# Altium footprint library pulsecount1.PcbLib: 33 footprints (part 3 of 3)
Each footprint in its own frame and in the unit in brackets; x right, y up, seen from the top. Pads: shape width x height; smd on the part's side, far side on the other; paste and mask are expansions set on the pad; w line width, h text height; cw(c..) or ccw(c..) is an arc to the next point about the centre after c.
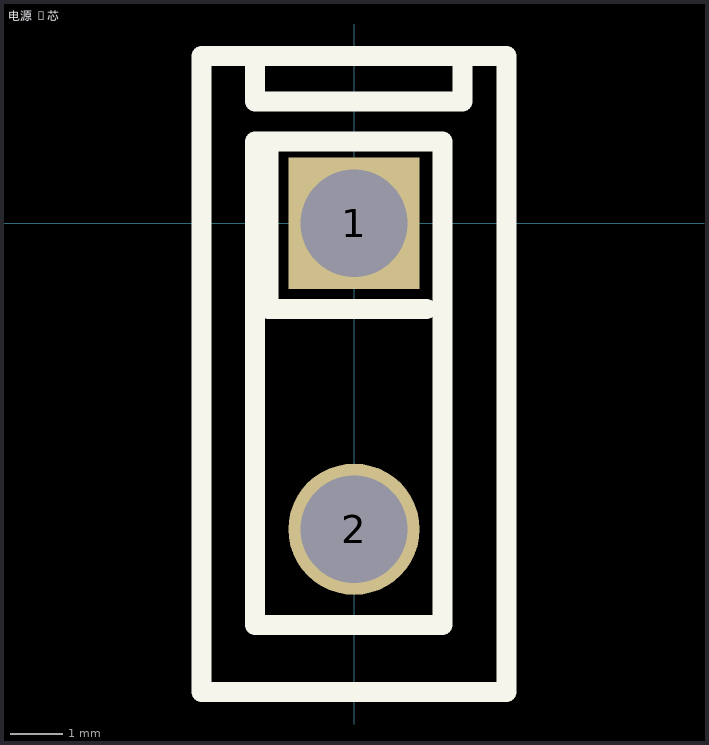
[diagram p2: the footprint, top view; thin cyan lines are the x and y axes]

## 电源 2芯 [mil]
pads (2):
  rect 98x98 hole 80: 1(0,0)
  round 98 hole 80: 2(0,-228.35)
Top Overlay:
  lines w15: -74,122 -74,91 81,91 81,117 ; -64,55 -64,-64 53.94,-64 ; -114,-350 113.94,-350 113.94,125 -114,125 -114,-350 ; -74,-300 -74,61 66,61 66,-300 -74,-300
